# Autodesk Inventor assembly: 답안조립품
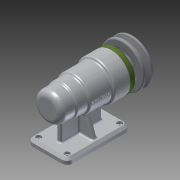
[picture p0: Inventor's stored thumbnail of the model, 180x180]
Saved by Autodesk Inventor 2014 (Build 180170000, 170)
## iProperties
Created: 2016-06
Part Number: 답안조립품
Document SubType Name: Assembly
Designer: USER
Author: USER
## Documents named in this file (12)
- C:\Users\USER\Desktop\460607V1022\답안조립품.iam
- C:\Users\USER\Desktop\460607V1022\본체.ipt
- C:\Users\USER\Desktop\460607V1022\V벨트풀리.ipt
- C:\Users\USER\Desktop\460607V1022\멈춤나사 M3x8.ipt
- C:\Users\USER\Desktop\460607V1022\베어링 6004.ipt
- C:\Users\USER\Desktop\460607V1022\베어링 51202.ipt
- C:\Users\USER\Desktop\460607V1022\볼트 M4 x 12.ipt
- C:\Users\USER\Desktop\460607V1022\어댑터슬리브.ipt
- C:\Users\USER\Desktop\460607V1022\오일 실.ipt
- C:\Users\USER\Desktop\460607V1022\축.ipt
- C:\Users\USER\Desktop\460607V1022\커버.ipt
- C:\Users\USER\Desktop\460607V1022\키 5 x 5 x 16.ipt
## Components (6 placed, 2 different names)
1. V벨트풀리:1
2. ISO 4762 M4 x 12:5
3. ISO 4762 M4 x 12:1
4. ISO 4762 M4 x 12:2
5. ISO 4762 M4 x 12:3
6. ISO 4762 M4 x 12:4
